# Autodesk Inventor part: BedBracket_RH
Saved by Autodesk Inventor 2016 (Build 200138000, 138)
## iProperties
Created: 2016-03
Part Number: BedBracket_RH
Material: Generic
Document SubType Name: Modeling
Designer: bongo_000
Density: 1 g/cm^3
Appearance: Default
Author: bongo_000
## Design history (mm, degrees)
feature "Base1"
body "Solid1"
